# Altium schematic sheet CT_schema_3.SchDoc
size 517 x 390 mm
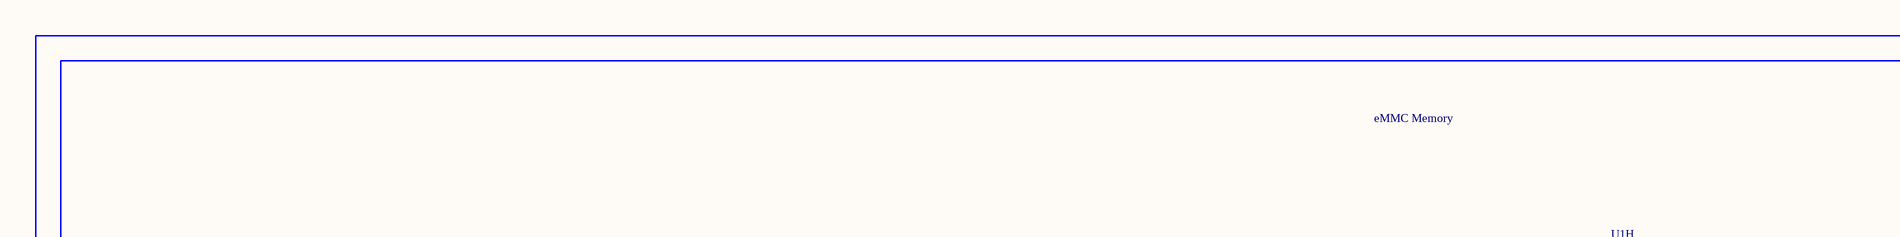
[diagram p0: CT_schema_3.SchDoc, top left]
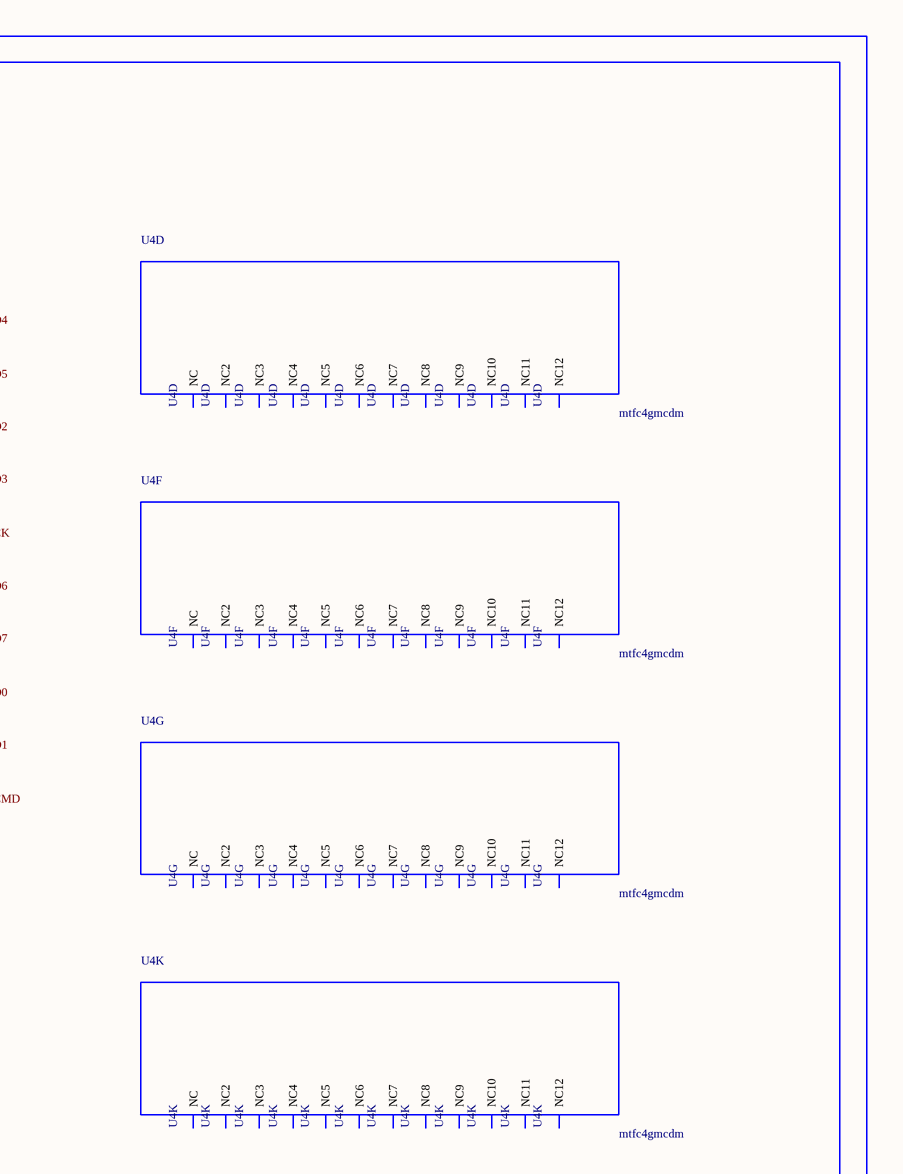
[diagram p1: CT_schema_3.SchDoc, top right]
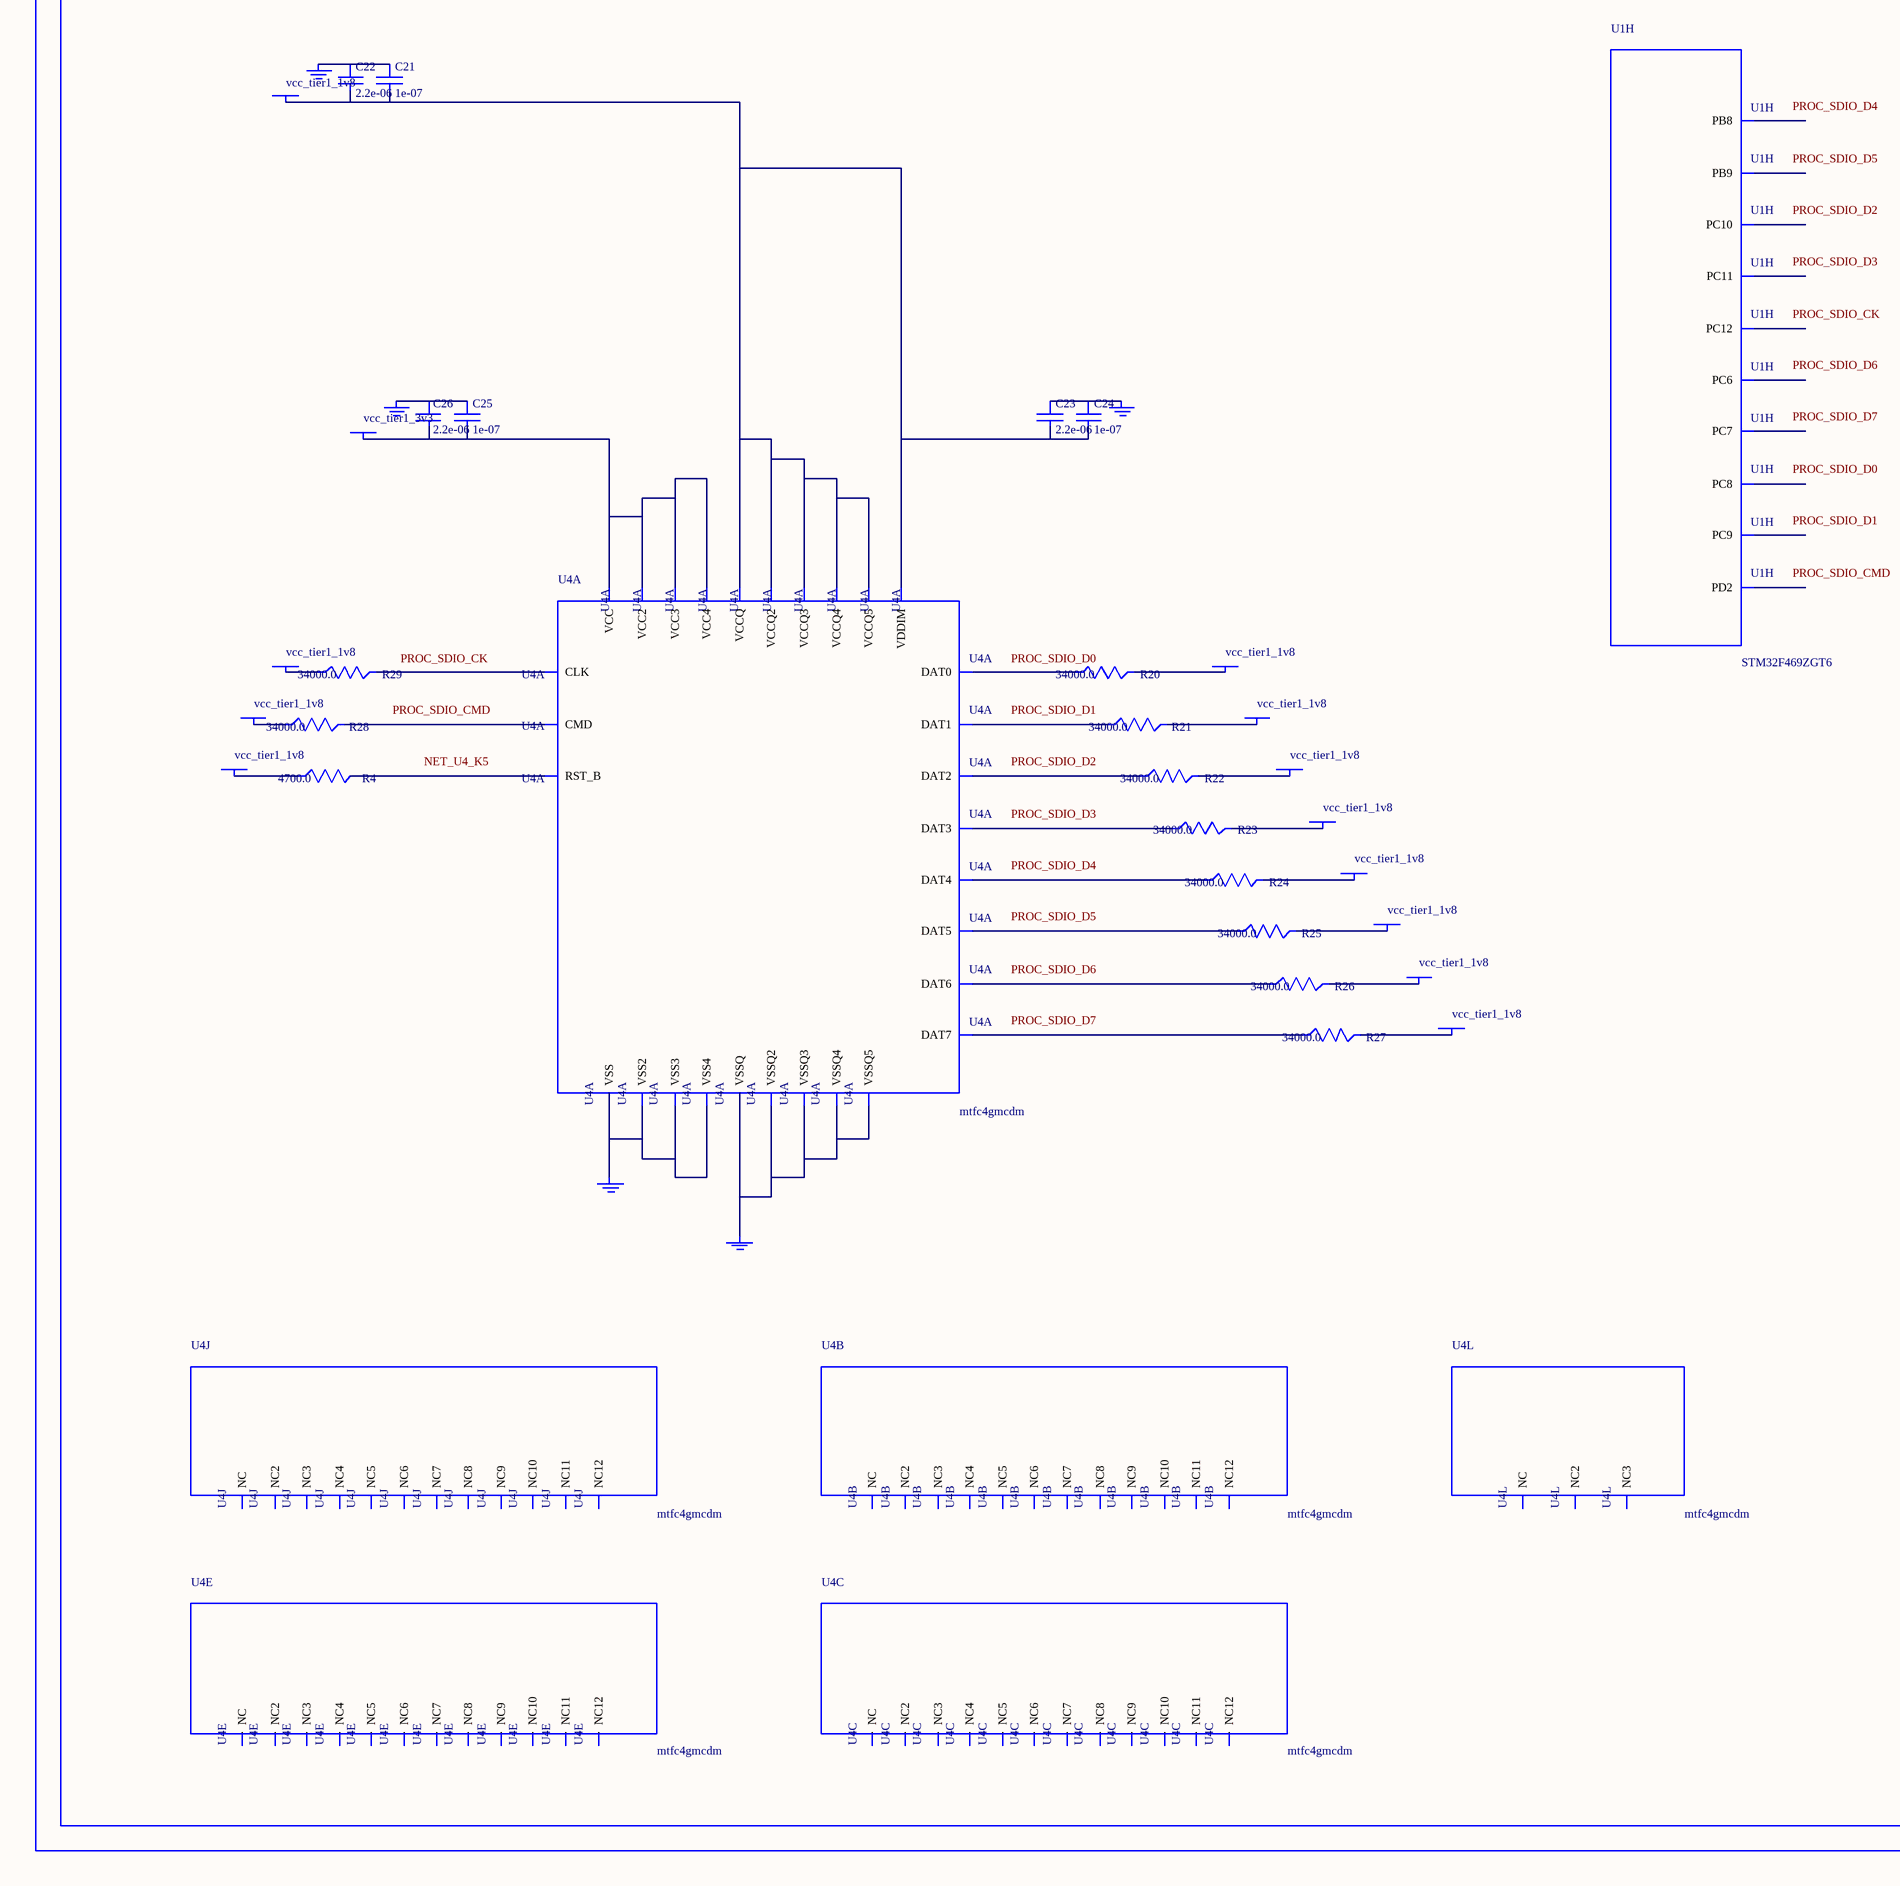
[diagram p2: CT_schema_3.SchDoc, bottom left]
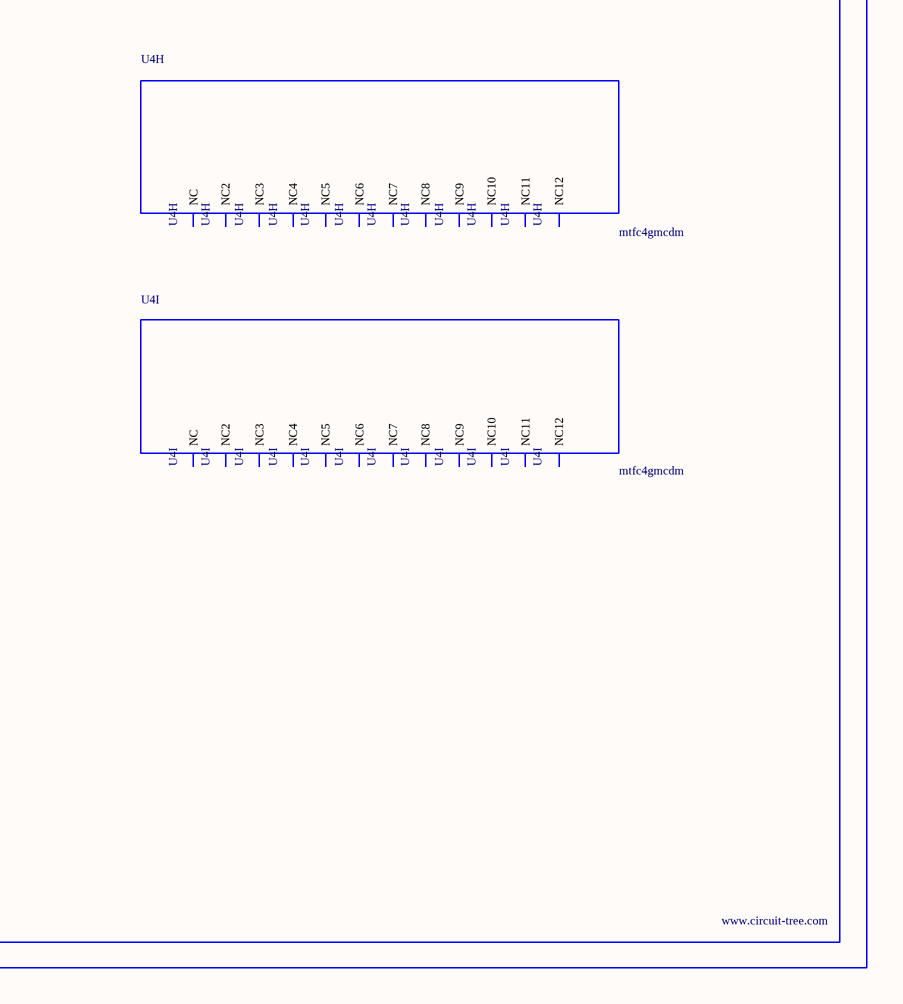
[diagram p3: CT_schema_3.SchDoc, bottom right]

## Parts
BORDER2  (no value)
C21  1e-07  [C0402]
C22  2.2e-06  [C0603]
C23  2.2e-06  [C0603]
C24  1e-07  [C0402]
C25  1e-07  [C0402]
C26  2.2e-06  [C0603]
GND_INSTANCE_2_0  (no value)
GND_INSTANCE_2_1  (no value)
GND_INSTANCE_2_2  (no value)
GND_INSTANCE_2_3  (no value)
GND_INSTANCE_2_4  (no value)
POWER_INSTANCE_2_0  vcc_tier1_1v8
POWER_INSTANCE_2_1  vcc_tier1_3v3
POWER_INSTANCE_2_2  vcc_tier1_1v8
POWER_INSTANCE_2_3  vcc_tier1_1v8
POWER_INSTANCE_2_4  vcc_tier1_1v8
POWER_INSTANCE_2_5  vcc_tier1_1v8
POWER_INSTANCE_2_6  vcc_tier1_1v8
POWER_INSTANCE_2_7  vcc_tier1_1v8
POWER_INSTANCE_2_8  vcc_tier1_1v8
POWER_INSTANCE_2_9  vcc_tier1_1v8
POWER_INSTANCE_2_10  vcc_tier1_1v8
POWER_INSTANCE_2_11  vcc_tier1_1v8
POWER_INSTANCE_2_12  vcc_tier1_1v8
R4  4700.0  [R0603]
R20  34000.0  [R0603]
R21  34000.0  [R0603]
R22  34000.0  [R0603]
R23  34000.0  [R0603]
R24  34000.0  [R0603]
R25  34000.0  [R0603]
R26  34000.0  [R0603]
R27  34000.0  [R0603]
R28  34000.0  [R0603]
R29  34000.0  [R0603]
U1  STM32F469ZGT6  [LQFP144]  (part H of 12)
U4  mtfc4gmcdm  [TFBGA-153]  (parts A,B,C,D,E,F,G,H,I,J,K,L of 12)

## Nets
NetC21_1: C21.1 C22.1 GND_INSTANCE_2_0.0(GND)
NetC21_2: C21.2 C22.2 C23.2 C24.2 POWER_INSTANCE_2_0.0(PWR) U4.C2(VDDIM) U4.C6(VCCQ) U4.M4(VCCQ2) U4.N4(VCCQ3) U4.P3(VCCQ4) U4.P5(VCCQ5)
NetC23_1: C23.1 C24.1 GND_INSTANCE_2_1.0(GND)
NetC25_1: C25.1 C26.1 GND_INSTANCE_2_2.0(GND)
NetC25_2: C25.2 C26.2 POWER_INSTANCE_2_1.0(PWR) U4.E6(VCC) U4.F5(VCC2) U4.J10(VCC3) U4.K9(VCC4)
NetGND_INSTANCE_2_3_0: GND_INSTANCE_2_3.0(GND) U4.E7(VSS) U4.G5(VSS2) U4.H10(VSS3) U4.K8(VSS4)
NetGND_INSTANCE_2_4_0: GND_INSTANCE_2_4.0(GND) U4.C4(VSSQ) U4.N2(VSSQ2) U4.N5(VSSQ3) U4.P4(VSSQ4) U4.P6(VSSQ5)
NetPOWER_INSTANCE_2_2_0: POWER_INSTANCE_2_2.0(PWR) R20.2
NetPOWER_INSTANCE_2_3_0: POWER_INSTANCE_2_3.0(PWR) R21.2
NetPOWER_INSTANCE_2_4_0: POWER_INSTANCE_2_4.0(PWR) R22.2
NetPOWER_INSTANCE_2_5_0: POWER_INSTANCE_2_5.0(PWR) R23.2
NetPOWER_INSTANCE_2_6_0: POWER_INSTANCE_2_6.0(PWR) R24.2
NetPOWER_INSTANCE_2_7_0: POWER_INSTANCE_2_7.0(PWR) R25.2
NetPOWER_INSTANCE_2_8_0: POWER_INSTANCE_2_8.0(PWR) R26.2
NetPOWER_INSTANCE_2_9_0: POWER_INSTANCE_2_9.0(PWR) R27.2
NetPOWER_INSTANCE_2_10_0: POWER_INSTANCE_2_10.0(PWR) R28.1
NetPOWER_INSTANCE_2_11_0: POWER_INSTANCE_2_11.0(PWR) R29.1
NetPOWER_INSTANCE_2_12_0: POWER_INSTANCE_2_12.0(PWR) R4.1
NetR4_2: R4.2 U4.K5(RST_B)
NetR20_1: R20.1 U4.A3(DAT0)
NetR21_1: R21.1 U4.A4(DAT1)
NetR22_1: R22.1 U4.A5(DAT2)
NetR23_1: R23.1 U4.B2(DAT3)
NetR24_1: R24.1 U4.B3(DAT4)
NetR25_1: R25.1 U4.B4(DAT5)
NetR26_1: R26.1 U4.B5(DAT6)
NetR27_1: R27.1 U4.B6(DAT7)
NetR28_2: R28.2 U4.M5(CMD)
NetR29_2: R29.2 U4.M6(CLK)

Not connected (* = marked no-connect by the designer): U1 98(PC6) 99(PC7) 100(PC8) 101(PC9) 113(PC10) 114(PC11) 115(PC12) 118(PD2) 138(PB8) 139(PB9); U4 A1(NC) A2(NC7) A6(NC8) A7(NC9) A8(NC10) A9(NC11) A10(NC2) A11(NC3) A12(NC4) A13(NC5) A14(NC6) B1(NC12) B7(NC6) B8(NC7) B9(NC8) B10(NC) B11(NC2) B12(NC3) B13(NC4) B14(NC5) C1(NC9) C3(NC10) C5(NC11) C7(NC12) C8(NC6) C9(NC7) C10(NC) C11(NC2) C12(NC3) C13(NC4) C14(NC5) D1(NC8) D2(NC10) D3(NC11) D4(NC12) D12(NC9) D13(NC) D14(NC2) E1(NC3) E2(NC8) E3(NC9) E5(NC10) E8(NC11) E9(NC12) E10(NC4) E12(NC5) E13(NC6) E14(NC7) F1(NC) F2(NC6) F3(NC7) F10(NC2) F12(NC3) F13(NC4) F14(NC5) G1(NC8) G2(NC11) G3(NC12) G10(NC9) G12(NC10) G13(NC) G14(NC2) H1(NC3) H2(NC7) H3(NC8) H5(NC9) H12(NC4) H13(NC5) H14(NC6) J1(NC10) J2(NC11) J3(NC12) J5(NC4) J12(NC) J13(NC2) J14(NC3) K1(NC5) K2(NC9) K3(NC10) K6(NC11) K7(NC12) K10(NC6) K12(NC7) K13(NC8) K14(NC) L1(NC2) L2(NC6) L3(NC7) L12(NC3) L13(NC4) L14(NC5) M1(NC8) M2(NC9) M3(NC10) M7(NC11) M8(NC12) M9(NC6) M10(NC) M11(NC2) M12(NC3) M13(NC4) M14(NC5) N1(NC7) N3(NC8) N6(NC9) N7(NC10) N8(NC11) N9(NC12) N10(NC) N11(NC2) N12(NC3) N13(NC4) N14(NC5) P1(NC6) P2(NC9) P7(NC10) P8(NC11) P9(NC12) P10(NC7) P11(NC8) P12(NC) P13(NC2) P14(NC3)

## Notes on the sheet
- Labels drawn without touching a wire or pin: NET_U4_K5, PROC_SDIO_CK, PROC_SDIO_CMD, PROC_SDIO_D0, PROC_SDIO_D1, PROC_SDIO_D2, PROC_SDIO_D3, PROC_SDIO_D4, PROC_SDIO_D5, PROC_SDIO_D6, PROC_SDIO_D7

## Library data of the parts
BORDER2 = BORDER_PAGE2
C21 C24 C25 = C0402C104K3RACTU
C22 C23 C26 = C0603C225K8RACTU
GND_INSTANCE_2_0-GND_INSTANCE_2_4 = GND
POWER_INSTANCE_2_0-POWER_INSTANCE_2_12 = PWR
R4 = RC0603JR-074K7L
R20-R29 = ERA3ARB3402V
